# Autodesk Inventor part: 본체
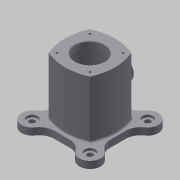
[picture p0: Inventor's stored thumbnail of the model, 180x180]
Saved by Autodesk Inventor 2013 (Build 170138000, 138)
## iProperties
Created: 2016-05
Part Number: 본체
Material: Generic
Document SubType Name: Modeling
Designer: Administrator
Density: 1 g/cm^3
Author: Administrator
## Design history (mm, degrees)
sketch "스케치1" dims "d2" = 100
  geometry: L1 (0, 0)-(68.866, 0); L2 (0, 0)-(46.209, 46.209); L3 (0, 0)-(0, 55.666); L4 (0, 0)-(-64.598, 0); A1 r 43 centre (0, 0) between (43, 0) and (0, 43); A2 r 97.722 centre (-54.687, -2.618) between (43, 0) and (35.355, 35.355); A3 r 96.975 centre (-2.457, -53.944) between (35.355, 35.355) and (0, 43); A4 r 96.975 centre (2.457, -53.944) between (0, 43) and (-35.355, 35.355); A5 r 97.722 centre (54.687, -2.618) between (-35.355, 35.355) and (-43, 0); A6 r 97.722 centre (54.687, 2.618) between (-43, 0) and (-35.355, -35.355); A7 r 96.975 centre (2.457, 53.944) between (-35.355, -35.355) and (0, -43); A8 r 96.975 centre (-2.457, 53.944) between (0, -43) and (35.355, -35.355); A9 r 97.722 centre (-54.687, 2.618) between (35.355, -35.355) and (43, 0); 1 further point
  constraints: 18 point on circle, 11 symmetric about line, 9 centre point, 8 end point, 3 point on line, 2 coincident, 2 perpendicular, 1 horizontal, 9 other
  dimensions: "d0" = 86 diameter of A1; "d3" = 45 deg angle of L2 L1; "d4" = 96.97525 radius of A3; "d5" = 97.72166 radius of A2
extrude "돌출1" new body sketch "스케치1" stored distance "d6" = 110; taper "d7" = 0 deg
sketch "스케치2"
  geometry: C1 r 35 at (0, 0); 1 further point
  constraints: 1 centre point, 1 coincident
  dimensions: "d8" = 70 diameter of C1
extrude "돌출2" cut sketch "스케치2" stored distance "d10" = 86; taper "d11" = 0 deg
sketch "스케치3"
  geometry: L1 (48, 13.489)-(48, -13.489); L2 (13.489, -48)-(-13.489, -48); L3 (-48, -13.489)-(-48, 13.489); L4 (0, 0)-(173.331, 0); L5 (0, 0)-(84.416, 84.416); L6 (-13.489, 48)-(13.489, 48); L7 (0, 0)-(0, 62.453); L8 (-13.489, -48)-(13.489, -48); A1 r 97.722 centre (54.687, -2.618) between (-35.355, 35.355) and (-43, 0) reference; A2 r 97.722 centre (54.687, 2.618) between (-43, 0) and (-35.355, -35.355) reference; A3 r 96.975 centre (2.457, 53.944) between (-35.355, -35.355) and (0, -43) reference; A4 r 96.975 centre (-2.457, 53.944) between (0, -43) and (35.355, -35.355) reference; A5 r 97.722 centre (-54.687, 2.618) between (35.355, -35.355) and (43, 0) reference; A6 r 97.722 centre (-54.687, -2.618) between (43, 0) and (35.355, 35.355) reference; A7 r 96.975 centre (-2.457, -53.944) between (35.355, 35.355) and (0, 43) reference; A8 r 96.975 centre (2.457, -53.944) between (0, 43) and (-35.355, 35.355) reference; A9 r 70 centre (0, 0) between (49.497, 49.497) and (60.531, 35.157); A10 r 18 centre (49.497, 49.497) between (59.336, 34.424) and (34.424, 59.336); A11 r 25 centre (13.489, 73) between (13.489, 48) and (34.424, 59.336); A12 r 25 centre (73, 13.489) between (59.336, 34.424) and (48, 13.489); A13 r 18 centre (-49.497, 49.497) between (-34.424, 59.336) and (-59.336, 34.424); A14 r 25 centre (-13.489, 73) between (-34.424, 59.336) and (-13.489, 48); A15 r 25 centre (-73, 13.489) between (-48, 13.489) and (-59.336, 34.424); A16 r 25 centre (-73, -13.489) between (-59.336, -34.424) and (-48, -13.489); A17 r 18 centre (-49.497, -49.497) between (-59.336, -34.424) and (-34.424, -59.336); A18 r 25 centre (-13.489, -73) between (-13.489, -48) and (-34.424, -59.336); A19 r 25 centre (13.489, -73) between (34.424, -59.336) and (13.489, -48); A20 r 18 centre (49.497, -49.497) between (34.424, -59.336) and (59.336, -34.424); A21 r 25 centre (73, -13.489) between (48, -13.489) and (59.336, -34.424); A22 r 97.722 centre (-54.687, -2.618) between (43, 0) and (35.355, 35.355); A23 r 96.975 centre (-2.457, 53.944) between (0, -43) and (35.355, -35.355); A24 r 96.975 centre (2.457, 53.944) between (-35.355, -35.355) and (0, -43); A25 r 97.722 centre (54.687, 2.618) between (-43, 0) and (-35.355, -35.355); A26 r 97.722 centre (54.687, -2.618) between (-35.355, 35.355) and (-43, 0); A27 r 96.975 centre (2.457, -53.944) between (0, 43) and (-35.355, 35.355); A28 r 96.975 centre (-2.457, -53.944) between (35.355, 35.355) and (0, 43); A29 r 97.722 centre (-54.687, 2.618) between (35.355, -35.355) and (43, 0); 8 further points
  constraints: 44 point on circle, 27 symmetric about line, 21 centre point, 16 end point, 8 concentric, 5 tangent, 2 perpendicular, 2 point on line, 1 coincident, 1 horizontal, 1 parallel, 9 other
  dimensions: "d15" = 48 distance from line of point (0, 0) L3 (= 0.5 x d12); "d17" = 140 diameter of A9; "d18" = 45 deg angle of L4 L5; "d19" = 36 diameter of A10; "d21" = 50 diameter of A11; "d22" = 50 diameter of A12; "d23" = 96 distance between parallel lines of L1 L3; "d24" = 48 distance from line of L6 point (0, 0); "d108" = 18 radius of A13 (derived)
extrude "돌출3" join sketch "스케치3" distance "d25" = 12; taper "d26" = 0 deg
sketch "스케치4"
  geometry: C1 r 5 at (-49.497, 49.497); C2 r 5 at (49.497, 49.497); C3 r 5 at (49.497, -49.497); C4 r 5 at (-49.497, -49.497); A1 r 18 centre (49.497, 49.497) between (59.336, 34.424) and (34.424, 59.336) reference; A2 r 18 centre (-49.497, 49.497) between (-34.424, 59.336) and (-59.336, 34.424) reference; A3 r 18 centre (-49.497, -49.497) between (-59.336, -34.424) and (-34.424, -59.336) reference; A4 r 18 centre (49.497, -49.497) between (34.424, -59.336) and (59.336, -34.424) reference; 1 further point
  constraints: 4 centre point, 4 coincident, 3 equal radius
  dimensions: "d27" = 10 diameter of C1
extrude "돌출4" cut sketch "스케치4" distance "d29" = 12; taper "d30" = 0 deg
sketch "스케치5"
  geometry: C1 r 5 at (49.497, -49.497) reference; C2 r 5 at (-49.497, 49.497) reference; C3 r 5 at (49.497, 49.497) reference; C4 r 5 at (-49.497, -49.497) reference; C5 r 9 at (-49.497, 49.497); C6 r 9 at (49.497, 49.497); C7 r 9 at (49.497, -49.497); C8 r 9 at (-49.497, -49.497); A1 r 18 centre (49.497, 49.497) between (59.336, 34.424) and (34.424, 59.336) reference; A2 r 18 centre (-49.497, 49.497) between (-34.424, 59.336) and (-59.336, 34.424) reference; A3 r 18 centre (-49.497, -49.497) between (-59.336, -34.424) and (-34.424, -59.336) reference; A4 r 18 centre (49.497, -49.497) between (34.424, -59.336) and (59.336, -34.424) reference; 1 further point
  constraints: 4 centre point, 4 coincident, 3 equal radius
  dimensions: "d31" = 18 diameter of C5
extrude "돌출5" cut sketch "스케치5" distance "d33" = 4; taper "d34" = 0 deg
sketch "스케치6"
  geometry: C1 r 25 at (0, 0); 1 further point
  constraints: 1 centre point, 1 coincident
  dimensions: "d35" = 50 diameter of C1
extrude "돌출6" cut sketch "스케치6" distance "d37" = 12; taper "d38" = 0 deg
fillet "모깎기1" dims "d39" = 3
node "작업 평면1"
chamfer "모따기1" distance "d53" = 1; stored, may be unused: second distance "d54" = 2, angle "d55" = 45 deg
sketch "스케치10" dims "d56" = 80
  geometry: L1 (0, 0)-(96.45, 0); L2 (0, 0)-(32.969, 32.969); C1 r 26 at (0, 0) reference; 1 further point
  constraints: 4 end point, 1 coincident, 1 horizontal, 1 point on line, 3 other
  dimensions: "d59" = 45 deg angle of L1 L2
hole "구멍1" sketch "스케치10" at (28.284, 28.284) diameter "d61" = 3.242; stored, may be unused: countersink angle "d65" = 90 deg, drill point angle "d67" = 118 deg; dims "d62" = 7, "d63" = 4, "d64" = 2, "d66" = 10
node "작업 평면2"
sketch "스케치11"
  geometry: L1 (0, 55)-(-35.355, 55) reference; 2 further points
  constraints: 1 other
  dimensions: "d72" = 49 distance from line of point (-29, 6) L1; "d73" = 29 horizontal distance of point (-29, 6) point (0, 0)
feature "엠보싱1" sketch "스케치11" dims "d0" = 86, "d2" = 100, "d3" = 45 deg, "d4" = 96.97525, "d5" = 97.72166, "d10" = 86, "d74" = 1, "d75" = 0
node "작업 평면3"
sketch "스케치15"
  geometry: L1 (0, 55)-(-35.355, 55) reference; L2 (0, -40)-(0, 55) reference; C1 r 20 at (0, 6); 1 further point
  constraints: 1 centre point, 1 point on line
  dimensions: "d90" = 40 diameter of C1; "d93" = 49 distance from line of L1 C1.centre
extrude "돌출10" join sketch "스케치15" stored distance "d94" = 8; taper "d95" = 10 deg
fillet "모깎기2" dims "d96" = 3
sketch "스케치16"
  geometry: C1 r 20 at (0, 6) reference; C2 r 15 at (0, 6); 1 further point
  constraints: 1 centre point, 1 coincident
  dimensions: "d97" = 30 diameter of C2
extrude "돌출11" cut sketch "스케치16" distance "d99" = 8; taper "d100" = 0 deg
sketch "스케치17"
  geometry: C1 r 20 at (0, 6) reference; C2 r 12.5 at (0, 6); 1 further point
  constraints: 1 centre point, 1 coincident
  dimensions: "d101" = 25 diameter of C2
extrude "돌출12" cut sketch "스케치17" stored distance "d103" = 8; taper "d104" = 0 deg
chamfer "모따기2" distance "d105" = 1; stored, may be unused: second distance "d106" = 2, angle "d107" = 45 deg
node "솔리드1"
mirror "대칭1"
pattern_circular "원형 패턴1" dims angle "d69" = 360 deg
mirror "대칭2"
other parameters: "d12" = 96, "d40" = 55, "d89" = 55
